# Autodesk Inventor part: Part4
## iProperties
Created: 2007-03
Part Number: Part4
Document SubType Name: Modeling
Designer: Administrator
Author: Administrator
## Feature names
1. Revolution1
2. Shell1
